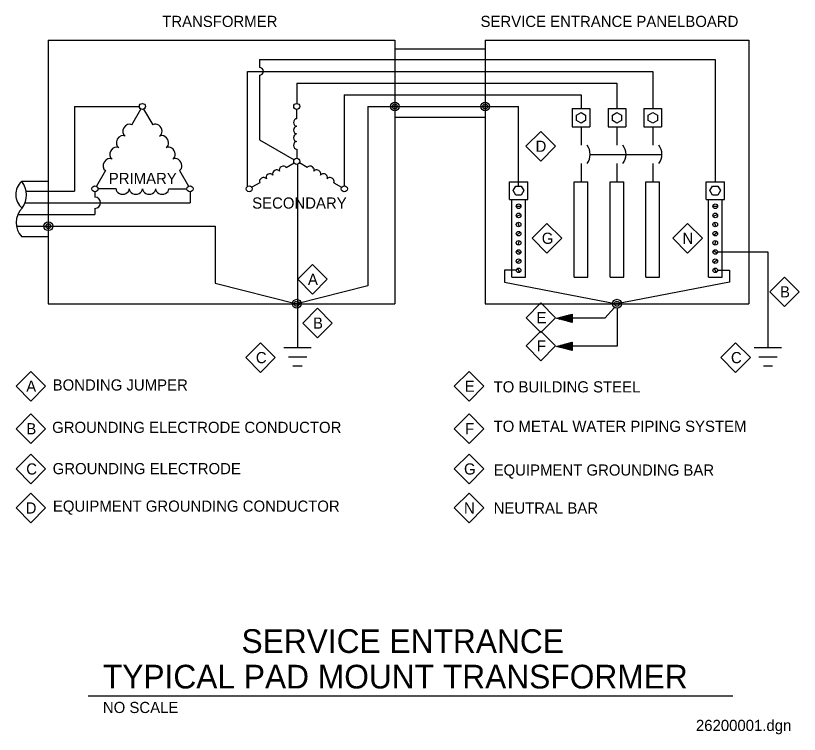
# Model space of a CAD drawing. Extents: x 10193.1 to 10240, y 10034.4 to 10077.4.
import ezdxf

# ---------------------------------------------------------------- set-up
doc = ezdxf.new("R2010")
doc.units = 0
for name, color, linetype in [('G-ANNO-TEXT', 7, 'Continuous'), ('G-DETL-LINE', 7, 'Continuous'), ('G-DETL-OTLN', 7, 'Continuous')]:
    doc.layers.add(name, color=color, linetype=linetype)

msp = doc.modelspace()

# ---------------------------------------------------------------- linework, layer by layer
at = {"layer": 'G-ANNO-TEXT'}
msp.add_line((10197.46, 10036.713), (10235.985, 10036.713), dxfattribs=at)
for points in [[(10224.5, 10068.671), (10223.617, 10069.555), (10224.5, 10070.439), (10225.384, 10069.555)], [(10224.867, 10063.172), (10223.983, 10064.055), (10224.867, 10064.939), (10225.751, 10064.055)], [(10233.273, 10063.172), (10232.39, 10064.055), (10233.273, 10064.939), (10234.157, 10064.055)], [(10210.863, 10060.718), (10209.98, 10061.602), (10210.863, 10062.486), (10211.747, 10061.602)], [(10239.067, 10059.97), (10238.183, 10060.854), (10239.067, 10061.738), (10239.951, 10060.854)], [(10224.505, 10058.425), (10223.621, 10059.308), (10224.505, 10060.192), (10225.389, 10059.308)], [(10211.162, 10058.101), (10210.278, 10058.985), (10211.162, 10059.869), (10212.046, 10058.985)], [(10224.505, 10056.737), (10223.621, 10057.621), (10224.505, 10058.505), (10225.389, 10057.621)], [(10207.753, 10056.039), (10206.869, 10056.923), (10207.753, 10057.807), (10208.637, 10056.923)], [(10236.141, 10056.039), (10235.257, 10056.923), (10236.141, 10057.807), (10237.025, 10056.923)], [(10194.033, 10054.329), (10193.15, 10055.213), (10194.033, 10056.096), (10194.917, 10055.213)], [(10220.221, 10054.329), (10219.337, 10055.213), (10220.221, 10056.096), (10221.104, 10055.213)], [(10194.033, 10051.788), (10193.15, 10052.671), (10194.033, 10053.555), (10194.917, 10052.671)], [(10220.221, 10051.788), (10219.337, 10052.671), (10220.221, 10053.555), (10221.104, 10052.671)], [(10194.033, 10049.384), (10193.15, 10050.267), (10194.033, 10051.151), (10194.917, 10050.267)], [(10220.221, 10049.384), (10219.337, 10050.267), (10220.221, 10051.151), (10221.104, 10050.267)], [(10194.033, 10047.051), (10193.15, 10047.935), (10194.033, 10048.818), (10194.917, 10047.935)], [(10220.221, 10047.051), (10219.337, 10047.935), (10220.221, 10048.818), (10221.104, 10047.935)]]:
    msp.add_lwpolyline(points, close=True, dxfattribs=at)
at = {"layer": 'G-DETL-LINE'}
for p, q in [((10207.695, 10074.733), (10234.927, 10074.733)), ((10207.695, 10074.733), (10207.695, 10074.253)), ((10234.927, 10074.733), (10234.927, 10067.43)), ((10206.988, 10074.033), (10231.195, 10074.033)), ((10206.988, 10067.169), (10206.988, 10074.033)), ((10231.195, 10074.033), (10231.195, 10071.805)), ((10207.695, 10073.805), (10207.695, 10069.937)), ((10209.92, 10073.333), (10209.92, 10072.115)), ((10209.92, 10073.333), (10229.051, 10073.333)), ((10229.051, 10073.333), (10229.051, 10071.805)), ((10212.762, 10072.633), (10212.762, 10067.193)), ((10212.762, 10072.633), (10226.907, 10072.633)), ((10226.907, 10072.633), (10226.907, 10071.805)), ((10196.634, 10071.933), (10200.52, 10071.933)), ((10196.634, 10071.933), (10196.634, 10066.875)), ((10200.07, 10070.839), (10200.611, 10071.775)), ((10201.333, 10070.839), (10200.793, 10071.775)), ((10209.92, 10071.204), (10209.92, 10071.75)), ((10214.162, 10071.933), (10223.175, 10071.933)), ((10214.162, 10071.933), (10214.162, 10061.214)), ((10223.175, 10067.177), (10223.175, 10071.933)), ((10226.382, 10071.805), (10226.382, 10070.711)), ((10226.382, 10071.805), (10227.432, 10071.805)), ((10227.432, 10071.805), (10227.432, 10070.711)), ((10228.526, 10071.805), (10228.526, 10070.711)), ((10228.526, 10071.805), (10229.576, 10071.805)), ((10229.576, 10071.805), (10229.576, 10070.711)), ((10230.67, 10071.805), (10230.67, 10070.711)), ((10230.67, 10071.805), (10231.72, 10071.805)), ((10231.72, 10071.805), (10231.72, 10070.711)), ((10226.382, 10070.711), (10227.432, 10070.711)), ((10226.907, 10070.711), (10226.907, 10069.617)), ((10228.526, 10070.711), (10229.576, 10070.711)), ((10229.051, 10070.711), (10229.051, 10069.617)), ((10230.67, 10070.711), (10231.72, 10070.711)), ((10231.195, 10070.711), (10231.195, 10069.617)), ((10207.695, 10069.937), (10209.763, 10068.743)), ((10209.92, 10069.381), (10209.92, 10068.834)), ((10227.454, 10069.07), (10231.742, 10069.07)), ((10209.289, 10068.287), (10209.763, 10068.56)), ((10209.968, 10068.475), (10209.968, 10057.521)), ((10210.552, 10068.287), (10210.078, 10068.56)), ((10226.907, 10068.523), (10226.907, 10067.43)), ((10229.051, 10068.523), (10229.051, 10067.43)), ((10231.195, 10068.523), (10231.195, 10067.43)), ((10198.492, 10068.105), (10197.951, 10067.169)), ((10202.912, 10068.105), (10203.452, 10067.169)), ((10222.628, 10066.38), (10222.628, 10067.43)), ((10222.628, 10067.43), (10223.722, 10067.43)), ((10223.722, 10066.38), (10223.722, 10067.43)), ((10226.497, 10061.731), (10226.497, 10067.43)), ((10226.497, 10067.43), (10227.318, 10067.43)), ((10227.318, 10061.731), (10227.318, 10067.43)), ((10228.641, 10061.731), (10228.641, 10067.43)), ((10228.641, 10067.43), (10229.461, 10067.43)), ((10229.461, 10061.731), (10229.461, 10067.43)), ((10230.785, 10061.731), (10230.785, 10067.43)), ((10230.785, 10067.43), (10231.605, 10067.43)), ((10231.605, 10061.731), (10231.605, 10067.43)), ((10234.38, 10066.38), (10234.38, 10067.43)), ((10234.38, 10067.43), (10235.474, 10067.43)), ((10235.474, 10066.38), (10235.474, 10067.43)), ((10199.123, 10067.011), (10198.042, 10067.011)), ((10202.281, 10067.011), (10203.361, 10067.011)), ((10207.71, 10067.375), (10207.237, 10067.102)), ((10212.131, 10067.375), (10212.604, 10067.102)), ((10193.745, 10066.875), (10196.634, 10066.875)), ((10197.86, 10066.829), (10197.86, 10066.511)), ((10203.543, 10066.829), (10203.543, 10066.175)), ((10193.683, 10066.175), (10203.543, 10066.175)), ((10222.628, 10066.38), (10223.722, 10066.38)), ((10222.765, 10061.731), (10222.765, 10066.38)), ((10223.585, 10061.731), (10223.585, 10066.38)), ((10234.38, 10066.38), (10235.474, 10066.38)), ((10234.517, 10061.731), (10234.517, 10066.38)), ((10235.337, 10061.731), (10235.337, 10066.38)), ((10197.86, 10065.84), (10197.86, 10065.475)), ((10223.038, 10065.969), (10223.312, 10065.969)), ((10234.79, 10065.969), (10235.064, 10065.969)), ((10193.252, 10065.475), (10197.86, 10065.475)), ((10223.047, 10065.376), (10223.304, 10065.469)), ((10234.798, 10065.376), (10235.055, 10065.469)), ((10193.17, 10064.775), (10205.042, 10064.775)), ((10205.042, 10064.775), (10205.042, 10061.374)), ((10223.222, 10064.747), (10223.128, 10065.004)), ((10234.974, 10064.747), (10234.88, 10065.004)), ((10223.07, 10064.241), (10223.28, 10064.417)), ((10234.822, 10064.241), (10235.032, 10064.417)), ((10223.128, 10063.653), (10223.222, 10063.91)), ((10234.88, 10063.653), (10234.974, 10063.91)), ((10223.294, 10063.167), (10223.057, 10063.303)), ((10235.045, 10063.167), (10234.809, 10063.303)), ((10235.064, 10063.235), (10238.074, 10063.235)), ((10235.064, 10063.235), (10238.074, 10063.235)), ((10238.074, 10063.235), (10238.074, 10057.521)), ((10223.07, 10062.6), (10223.28, 10062.776)), ((10234.822, 10062.6), (10235.032, 10062.776)), ((10223.244, 10062.023), (10223.107, 10062.26)), ((10234.995, 10062.023), (10234.859, 10062.26)), ((10205.042, 10061.374), (10209.92, 10060.143)), ((10222.765, 10061.731), (10223.585, 10061.731)), ((10226.497, 10061.731), (10227.318, 10061.731)), ((10228.641, 10061.731), (10229.461, 10061.731)), ((10230.785, 10061.731), (10231.605, 10061.731)), ((10234.517, 10061.731), (10235.337, 10061.731)), ((10214.162, 10061.214), (10209.92, 10060.143)), ((10228.323, 10059.29), (10228.905, 10059.918)), ((10225.791, 10059.181), (10226.051, 10059.441)), ((10225.864, 10059.161), (10226.177, 10059.474)), ((10225.937, 10059.142), (10226.304, 10059.508)), ((10226.011, 10059.122), (10226.379, 10059.49)), ((10226.062, 10059.444), (10226.379, 10059.128)), ((10226.136, 10059.463), (10226.379, 10059.22)), ((10226.209, 10059.483), (10226.379, 10059.313)), ((10226.282, 10059.502), (10226.379, 10059.406)), ((10226.356, 10059.522), (10226.379, 10059.499)), ((10229.076, 10059.865), (10229.076, 10057.61)), ((10225.476, 10059.288), (10225.508, 10059.256)), ((10225.498, 10059.259), (10225.545, 10059.306)), ((10228.323, 10059.29), (10225.528, 10059.29)), ((10225.549, 10059.307), (10225.634, 10059.222)), ((10225.571, 10059.239), (10225.671, 10059.34)), ((10225.623, 10059.327), (10225.761, 10059.189)), ((10225.644, 10059.22), (10225.798, 10059.373)), ((10225.696, 10059.346), (10225.887, 10059.155)), ((10225.717, 10059.2), (10225.924, 10059.407)), ((10225.769, 10059.366), (10226.014, 10059.121)), ((10225.843, 10059.385), (10226.14, 10059.088)), ((10225.916, 10059.405), (10226.267, 10059.054)), ((10225.989, 10059.424), (10226.379, 10059.035)), ((10226.084, 10059.103), (10226.379, 10059.398)), ((10226.157, 10059.083), (10226.379, 10059.305)), ((10226.23, 10059.064), (10226.379, 10059.212)), ((10226.304, 10059.044), (10226.379, 10059.119)), ((10226.377, 10059.025), (10226.379, 10059.026)), ((10225.476, 10057.608), (10225.508, 10057.576)), ((10225.498, 10057.579), (10225.545, 10057.626)), ((10229.076, 10057.61), (10225.528, 10057.61)), ((10225.549, 10057.627), (10225.634, 10057.543)), ((10225.571, 10057.56), (10225.671, 10057.66)), ((10225.623, 10057.647), (10225.761, 10057.509)), ((10225.644, 10057.54), (10225.798, 10057.694)), ((10225.696, 10057.666), (10225.887, 10057.475)), ((10225.717, 10057.521), (10225.924, 10057.727)), ((10225.769, 10057.686), (10226.014, 10057.442)), ((10225.791, 10057.501), (10226.051, 10057.761)), ((10225.843, 10057.706), (10226.14, 10057.408)), ((10225.864, 10057.481), (10226.177, 10057.795)), ((10225.916, 10057.725), (10226.267, 10057.374)), ((10225.937, 10057.462), (10226.304, 10057.828)), ((10225.989, 10057.745), (10226.379, 10057.355)), ((10226.011, 10057.442), (10226.379, 10057.811)), ((10226.062, 10057.764), (10226.379, 10057.448)), ((10226.084, 10057.423), (10226.379, 10057.718)), ((10226.136, 10057.784), (10226.379, 10057.541)), ((10226.157, 10057.403), (10226.379, 10057.625)), ((10226.209, 10057.803), (10226.379, 10057.633)), ((10226.282, 10057.823), (10226.379, 10057.726)), ((10226.356, 10057.842), (10226.379, 10057.819)), ((10209.147, 10057.521), (10210.788, 10057.521)), ((10226.23, 10057.384), (10226.379, 10057.532)), ((10226.304, 10057.364), (10226.379, 10057.439)), ((10226.377, 10057.345), (10226.379, 10057.347)), ((10237.254, 10057.521), (10238.895, 10057.521)), ((10209.421, 10056.974), (10210.514, 10056.974)), ((10237.527, 10056.974), (10238.621, 10056.974)), ((10209.694, 10056.427), (10210.241, 10056.427)), ((10237.801, 10056.427), (10238.348, 10056.427))]:
    msp.add_line(p, q, dxfattribs=at)
for points in [[(10226.907, 10071.572), (10227.18, 10071.415), (10227.18, 10071.1), (10226.907, 10070.943), (10226.635, 10071.1), (10226.635, 10071.415)], [(10229.051, 10071.572), (10229.323, 10071.415), (10229.323, 10071.1), (10229.051, 10070.943), (10228.779, 10071.1), (10228.779, 10071.415)], [(10231.195, 10071.572), (10231.467, 10071.415), (10231.467, 10071.1), (10231.195, 10070.943), (10230.922, 10071.1), (10230.922, 10071.415)], [(10222.861, 10066.905), (10223.018, 10067.177), (10223.332, 10067.177), (10223.49, 10066.905), (10223.332, 10066.632), (10223.018, 10066.632)], [(10234.613, 10066.905), (10234.77, 10067.177), (10235.084, 10067.177), (10235.241, 10066.905), (10235.084, 10066.632), (10234.77, 10066.632)], [(10225.433, 10059.276), (10226.379, 10059.528), (10226.379, 10059.024)], [(10225.433, 10057.596), (10226.379, 10057.848), (10226.379, 10057.344)]]:
    msp.add_lwpolyline(points, close=True, dxfattribs=at)
for points in [[(10223.038, 10062.141), (10222.328, 10062.141), (10222.328, 10061.425)], [(10235.064, 10062.141), (10235.774, 10062.141), (10235.774, 10061.425)], [(10222.328, 10061.425), (10229.051, 10060.143)], [(10235.774, 10061.425), (10229.051, 10060.143)]]:
    msp.add_lwpolyline(points, dxfattribs=at)
for centre, radius in [((10200.702, 10071.933), 0.182), ((10209.92, 10071.933), 0.182), ((10215.784, 10071.933), 0.263), ((10221.177, 10071.933), 0.263), ((10215.784, 10071.933), 0.148), ((10215.784, 10071.933), 0.0492), ((10221.177, 10071.933), 0.148), ((10221.177, 10071.933), 0.0492), ((10209.92, 10068.652), 0.182), ((10209.92, 10068.652), 0.182), ((10209.92, 10068.652), 0.182), ((10197.86, 10067.011), 0.182), ((10203.543, 10067.011), 0.182), ((10207.079, 10067.011), 0.182), ((10212.762, 10067.011), 0.182), ((10223.175, 10065.969), 0.137), ((10234.927, 10065.969), 0.137), ((10223.175, 10065.423), 0.137), ((10234.927, 10065.423), 0.137), ((10195.076, 10064.775), 0.263), ((10195.076, 10064.775), 0.148), ((10195.076, 10064.775), 0.0492), ((10223.175, 10064.876), 0.137), ((10234.927, 10064.876), 0.137), ((10223.175, 10064.329), 0.137), ((10234.927, 10064.329), 0.137), ((10223.175, 10063.782), 0.137), ((10234.927, 10063.782), 0.137), ((10223.175, 10063.235), 0.137), ((10234.927, 10063.235), 0.137), ((10223.175, 10062.688), 0.137), ((10234.927, 10062.688), 0.137), ((10223.175, 10062.141), 0.137), ((10234.927, 10062.141), 0.137), ((10209.92, 10060.143), 0.263), ((10229.057, 10060.143), 0.263), ((10209.92, 10060.143), 0.148), ((10209.92, 10060.143), 0.0492), ((10229.057, 10060.143), 0.148), ((10229.057, 10060.143), 0.0492)]:
    msp.add_circle(centre, radius, dxfattribs=at)
for centre, radius, start, end in [((10207.692, 10074.031), 0.233, 270.0197, 89.9803), ((10226.543, 10069.07), 0.911, 323.1301, 36.8699), ((10228.686, 10069.07), 0.911, 323.1301, 36.8699), ((10230.83, 10069.07), 0.911, 323.1301, 36.8699), ((10197.86, 10066.175), 0.335, 270.0011, 89.9989)]:
    msp.add_arc(centre, radius, start, end, dxfattribs=at)
for centre, major_axis, start_param, end_param in [((10209.92, 10070.976), (0, -0.228), 3.141593, 6.283185), ((10199.873, 10070.497), (-0.197, -0.342), 3.141593, 6.283185), ((10201.531, 10070.497), (0.197, -0.342), 0, 3.141593), ((10209.92, 10070.52), (0, -0.228), 3.141593, 6.283185), ((10199.478, 10069.814), (-0.197, -0.342), 3.141593, 6.283185), ((10201.925, 10069.814), (0.197, -0.342), 0, 3.141593), ((10209.92, 10070.064), (0, -0.228), 3.141593, 6.283185), ((10209.92, 10069.609), (0, -0.228), 3.141593, 6.283185), ((10199.084, 10069.13), (-0.197, -0.342), 3.141593, 6.283185), ((10202.32, 10069.13), (0.197, -0.342), 0, 3.141593), ((10198.689, 10068.446), (-0.197, -0.342), 3.141593, 6.283185), ((10202.715, 10068.446), (0.197, -0.342), 0, 3.141593), ((10209.092, 10068.173), (-0.197, -0.114), 3.141593, 6.283185), ((10210.749, 10068.173), (0.197, -0.114), 0, 3.141593), ((10208.302, 10067.717), (-0.197, -0.114), 3.141593, 6.283185), ((10208.697, 10067.945), (-0.197, -0.114), 3.141593, 6.283185), ((10211.144, 10067.945), (0.197, -0.114), 0, 3.141593), ((10211.539, 10067.717), (0.197, -0.114), 0, 3.141593), ((10207.908, 10067.489), (-0.197, -0.114), 3.141593, 6.283185), ((10211.933, 10067.489), (0.197, -0.114), 0, 3.141593), ((10199.518, 10067.011), (-0.395, 0), 0, 3.141593), ((10200.307, 10067.011), (-0.395, 0), 0, 3.141593), ((10201.097, 10067.011), (-0.395, 0), 0, 3.141593), ((10201.886, 10067.011), (-0.395, 0), 0, 3.141593)]:
    msp.add_ellipse(centre, major_axis=major_axis, ratio=0.816497, start_param=start_param, end_param=end_param, dxfattribs=at)
at = {"layer": 'G-DETL-OTLN'}
for p, q in [((10195.076, 10075.891), (10215.784, 10075.891)), ((10195.076, 10075.891), (10195.076, 10060.143)), ((10215.784, 10075.891), (10215.784, 10060.143)), ((10221.177, 10075.891), (10221.177, 10060.143)), ((10221.177, 10075.891), (10236.925, 10075.891)), ((10236.925, 10075.891), (10236.925, 10060.143)), ((10215.784, 10075.374), (10221.177, 10075.374)), ((10215.784, 10071.284), (10221.177, 10071.284)), ((10195.076, 10067.45), (10193.485, 10067.45)), ((10195.076, 10064.139), (10193.485, 10064.139)), ((10195.076, 10060.143), (10215.784, 10060.143)), ((10221.177, 10060.143), (10236.925, 10060.143))]:
    msp.add_line(p, q, dxfattribs=at)
for centre, radius, start, end in [((10194.157, 10066.668), 1.031, 130.6803, 231.3886), ((10192.452, 10066.637), 1.314, 323.868, 38.2009), ((10194.393, 10064.986), 1.241, 135.1065, 222.9865)]:
    msp.add_arc(centre, radius, start, end, dxfattribs=at)

# ---------------------------------------------------------------- texts
at = {"layer": 'G-ANNO-TEXT'}
for s, height, p in [('TRANSFORMER', 0.66667, (10201.882, 10076.684)), ('SERVICE ENTRANCE PANELBOARD', 0.66667, (10220.903, 10076.684)), ('D', 0.667, (10224.19, 10069.222)), ('PRIMARY', 0.6667, (10198.689, 10067.299)), ('SECONDARY', 0.6667, (10207.257, 10065.828)), ('G', 0.667, (10224.561, 10063.722)), ('N', 0.667, (10232.967, 10063.722)), ('A', 0.667, (10210.589, 10061.269)), ('B', 0.667, (10238.797, 10060.52)), ('E', 0.667, (10224.248, 10058.975)), ('B', 0.667, (10210.892, 10058.652)), ('F', 0.667, (10224.266, 10057.288)), ('C', 0.667, (10207.478, 10056.589)), ('C', 0.667, (10235.866, 10056.589)), ('A', 0.667, (10193.758, 10054.879)), ('BONDING JUMPER', 0.66667, (10195.337, 10054.955)), ('E', 0.667, (10219.963, 10054.879)), ('TO BUILDING STEEL', 0.66667, (10221.684, 10054.842)), ('B', 0.667, (10193.763, 10052.338)), ('GROUNDING ELECTRODE CONDUCTOR', 0.66667, (10195.303, 10052.421)), ('F', 0.667, (10219.982, 10052.338)), ('TO METAL WATER PIPING SYSTEM', 0.66667, (10221.684, 10052.485)), ('C', 0.667, (10193.758, 10049.934)), ('GROUNDING ELECTRODE', 0.66667, (10195.337, 10049.955)), ('G', 0.667, (10219.915, 10049.934)), ('EQUIPMENT GROUNDING BAR', 0.66667, (10221.684, 10049.87)), ('D', 0.667, (10193.723, 10047.601)), ('EQUIPMENT GROUNDING CONDUCTOR', 0.66667, (10195.351, 10047.712)), ('N', 0.667, (10219.915, 10047.601)), ('NEUTRAL BAR', 0.66667, (10221.684, 10047.598)), ('SERVICE ENTRANCE', 1.41667, (10206.621, 10039.271)), ('TYPICAL PAD MOUNT TRANSFORMER', 1.41667, (10198.338, 10037.146)), ('NO SCALE', 0.6667, (10198.338, 10035.679)), ('26200001.dgn', 0.66667, (10233.774, 10034.607))]:
    msp.add_text(s, height=height, dxfattribs=at).set_placement(p)

doc.saveas('drawing.dxf')
